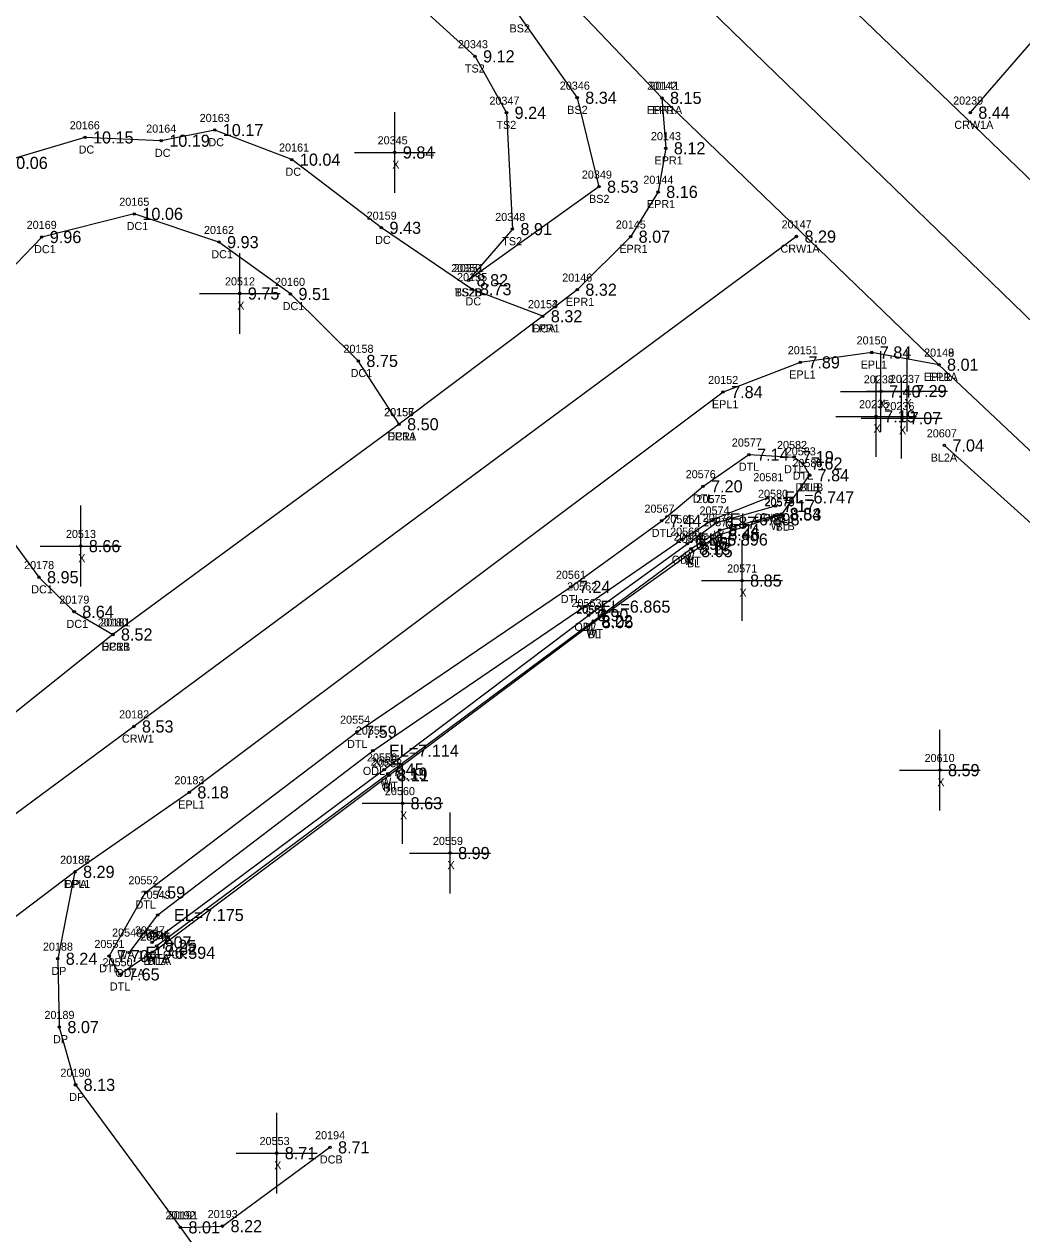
# Model space of a CAD drawing. Extents: x 2608745 to 2610333, y 641917 to 643463.
# Drawn here: x 2608960.7 to 2609084.1, y 642999.4 to 643149.1 of the extents above; entities that cross this region are included whole.
import ezdxf

# ---------------------------------------------------------------- set-up
doc = ezdxf.new("R2010")
doc.units = 0
for name, color, linetype in [('RD_DTM_BkLn1', 7, 'Continuous'), ('RD_DTM_BkLn2', 7, 'Continuous'), ('RD_DTM_BkLn_txCode', 7, 'Continuous'), ('RD_EX_BldgApp', 7, 'Continuous'), ('RD_EX_Conc', 7, 'Continuous'), ('RD_EX_Conc_txCode', 7, 'Continuous'), ('RD_EX_Driveway', 7, 'Continuous'), ('RD_EX_Driveway_txCode', 7, 'Continuous'), ('RD_EX_H2O', 7, 'Continuous'), ('RD_EX_H2O_txCode', 7, 'Continuous'), ('RD_EX_Misc', 7, 'Continuous'), ('RD_EX_Misc_txCode', 7, 'Continuous'), ('RD_EX_Road', 7, 'Continuous'), ('RD_EX_Road_txCode', 7, 'Continuous'), ('RD_EX_TX_Conc_ELEV', 7, 'Continuous'), ('RD_EX_TX_Driveway_ELEV', 7, 'Continuous'), ('RD_EX_TX_H2O_ELEV', 7, 'Continuous'), ('RD_EX_TX_Misc_ELEV', 7, 'Continuous'), ('RD_EX_TX_Road_ELEV', 7, 'Continuous'), ('RD_HC_Survey_ELEV', 7, 'Continuous'), ('RD_HC_Survey_txCode', 7, 'Continuous'), ('RD_SMD_Locator', 7, 'Continuous')]:
    doc.layers.add(name, color=color, linetype=linetype)

msp = doc.modelspace()

# ---------------------------------------------------------------- linework, layer by layer
at = {"layer": 'RD_DTM_BkLn1'}
for points in [[(2608814.73, 643373.65), (2608890.45, 643300.26), (2608962.19, 643231.31), (2609034.91, 643161.19), (2609108.48, 643089.9), (2609179.19, 643022.29), (2609255.71, 642948.78), (2609335.19, 642871.73), (2609410.7, 642798.48), (2609491.67, 642719.95), (2609518.07, 642695.15)], [(2609077.75, 643138.13), (2609090.47, 643152.84), (2609101.55, 643166.78), (2609119.24, 643191.44), (2609138.5, 643219.13), (2609195.83, 643301.54)], [(2609056.24, 643122.81), (2608974.26, 643062.19), (2608891.12, 643000.79)], [(2609074.55, 643096.96), (2609096.36, 643077.36), (2609116.48, 643056.4)], [(2608977.19, 643034.69), (2609005.85, 643056.15), (2609031.16, 643075.1), (2609043.45, 643083.89), (2609046.82, 643085.96), (2609054.43, 643088.41), (2609057.86, 643093.28)]]:
    msp.add_lwpolyline(points, dxfattribs=at)
at = {"layer": 'RD_DTM_BkLn2'}
for points in [[(2608924.3, 643237.42), (2608926.68, 643230.5), (2608943.06, 643211.67), (2609016.47, 643145.1), (2609020.37, 643138.12), (2609021.09, 643123.73), (2609015.67, 643117.4)], [(2608924.3, 643237.42), (2608928.82, 643236.52), (2608949.12, 643217.98), (2609021.97, 643150.06), (2609029.11, 643139.98), (2609031.81, 643128.97), (2609015.67, 643117.4)], [(2608977.07, 643035.04), (2609005.68, 643056.35), (2609031.1, 643075.23), (2609043.19, 643084.18), (2609046.77, 643086.49), (2609054.4, 643088.49)]]:
    msp.add_lwpolyline(points, dxfattribs=at)
at = {"layer": 'RD_EX_BldgApp'}
msp.add_lwpolyline([(2608976.5, 643035.47), (2609005.23, 643056.86), (2609030.55, 643075.96), (2609042.75, 643084.8), (2609046.37, 643087.41), (2609053.65, 643089.48)], dxfattribs=at)
at = {"layer": 'RD_EX_Conc'}
for points in [[(2609024.85, 643112.94), (2609016.08, 643116.29), (2609004.89, 643123.89), (2608993.8, 643132.32), (2608984.26, 643135.98), (2608977.64, 643134.66), (2608968.2, 643135.07), (2608957.58, 643131.92), (2608944.58, 643124.19), (2608938.75, 643122.14), (2608934.12, 643122.55)], [(2609007.07, 643099.58), (2609002.03, 643107.42), (2608993.62, 643115.7), (2608984.79, 643122.12), (2608974.31, 643125.61), (2608962.85, 643122.75), (2608953.28, 643112.83), (2608950.49, 643102.09), (2608953.24, 643093.2), (2608962.51, 643080.66), (2608966.87, 643076.38), (2608971.66, 643073.57)], [(2608980.01, 643000.22), (2608985.22, 643000.37), (2608998.52, 643010.12)]]:
    msp.add_lwpolyline(points, dxfattribs=at)
at = {"layer": 'RD_EX_Driveway'}
msp.add_lwpolyline([(2608966.97, 643044.2), (2608964.83, 643033.45), (2608965.03, 643025), (2608967.04, 643017.85), (2608980.01, 643000.22), (2609002.72, 642968.53)], dxfattribs=at)
at = {"layer": 'RD_EX_H2O'}
for points in [[(2608977.19, 643034.69), (2608972.54, 643031.52), (2608971.2, 643033.78), (2608975.7, 643041.66), (2609001.88, 643061.53), (2609028.33, 643079.46), (2609039.58, 643087.64), (2609044.68, 643091.9), (2609050.37, 643095.82), (2609055.96, 643095.52), (2609057.04, 643094.73), (2609057.86, 643093.28)], [(2608973.68, 643034.19), (2608977.21, 643038.87), (2609003.83, 643059.19), (2609030, 643077.02), (2609042.06, 643085.32), (2609045.99, 643087.82), (2609052.74, 643090.53)]]:
    msp.add_lwpolyline(points, dxfattribs=at)
at = {"layer": 'RD_EX_Misc'}
for p, q in [((2609006.54, 643128.21), (2609006.54, 643138.21)), ((2609001.54, 643133.21), (2609011.54, 643133.21)), ((2608987.36, 643110.76), (2608987.36, 643120.76)), ((2608982.36, 643115.76), (2608992.36, 643115.76)), ((2609066.7, 643098.64), (2609066.7, 643108.64)), ((2609069.93, 643098.69), (2609069.93, 643108.69)), ((2609066.1, 643095.56), (2609066.1, 643105.56)), ((2609069.26, 643095.34), (2609069.26, 643105.34)), ((2609061.7, 643103.64), (2609071.7, 643103.64)), ((2609064.93, 643103.69), (2609074.93, 643103.69)), ((2609061.1, 643100.56), (2609071.1, 643100.56)), ((2609064.26, 643100.34), (2609074.26, 643100.34)), ((2608967.68, 643079.51), (2608967.68, 643089.51)), ((2609049.51, 643075.24), (2609049.51, 643085.24)), ((2608962.68, 643084.51), (2608972.68, 643084.51)), ((2609044.51, 643080.24), (2609054.51, 643080.24)), ((2609074, 643051.79), (2609074, 643061.79)), ((2609007.5, 643047.69), (2609007.5, 643057.69)), ((2609069, 643056.79), (2609079, 643056.79)), ((2609002.5, 643052.69), (2609012.5, 643052.69)), ((2609013.38, 643041.53), (2609013.38, 643051.53)), ((2609008.38, 643046.53), (2609018.38, 643046.53)), ((2608991.93, 643004.4), (2608991.93, 643014.4)), ((2608986.93, 643009.4), (2608996.93, 643009.4))]:
    msp.add_line(p, q, dxfattribs=at)
at = {"layer": 'RD_EX_Road'}
for points in [[(2608806.89, 643364.99), (2608810.18, 643361.1), (2608820.75, 643351.25), (2608881.81, 643292.24), (2608917.83, 643257.49), (2608933.21, 643242.71), (2608954.07, 643222.83), (2609026.06, 643154.19), (2609039.6, 643139.96), (2609073.88, 643106.95), (2609100.48, 643081.89), (2609124.19, 643058.87), (2609171.61, 643013.71), (2609183.19, 643002.28), (2609197.91, 642988.37), (2609247.59, 642940.95), (2609328.02, 642863.6), (2609402.61, 642790.3), (2609474.23, 642720.69), (2609483.84, 642711.58), (2609495.78, 642699.92), (2609509.81, 642686.45)], [(2609058.51, 643155.46), (2609096.06, 643119.37), (2609116.51, 643099.11), (2609162.4, 643055.35), (2609177.21, 643041.34), (2609188.35, 643030.96), (2609199.91, 643019.76), (2609205.8, 643014.04), (2609217.13, 643003.17), (2609235.83, 642983.9), (2609237.03, 642983.51), (2609256.8, 642965.04), (2609258.49, 642962.51), (2609263.65, 642957.66), (2609344.71, 642879.89), (2609418.83, 642806.19), (2609500.61, 642728.46), (2609512.38, 642716.82), (2609526.19, 642703.5)], [(2609039.6, 643139.96), (2609040.08, 643133.73), (2609039.13, 643128.33), (2609035.72, 643122.79), (2609029.12, 643116.23), (2609024.85, 643112.94), (2609007.07, 643099.58), (2608971.66, 643073.57), (2608951.45, 643057.43), (2608918.97, 643034.33), (2608905.4, 643024.24), (2608885.4, 643009.36)], [(2609073.88, 643106.95), (2609065.56, 643108.46), (2609056.72, 643107.24), (2609047.16, 643103.56), (2608981.11, 643054.04), (2608966.97, 643044.2), (2608926.38, 643013.48), (2608922.5, 643010.56), (2608906.31, 642998.78), (2608898.21, 642992.72)]]:
    msp.add_lwpolyline(points, dxfattribs=at)
at = {"layer": 'RD_SMD_Locator'}
for centre in [(2609016.47, 643145.1), (2609029.11, 643139.98), (2609039.6, 643139.96), (2609039.6, 643139.96), (2609020.37, 643138.12), (2609077.75, 643138.13), (2608984.26, 643135.98), (2608968.2, 643135.07), (2608977.64, 643134.66), (2609006.54, 643133.21), (2609040.08, 643133.73), (2608993.8, 643132.32), (2609031.81, 643128.97), (2609039.13, 643128.33), (2608974.31, 643125.61), (2608962.85, 643122.75), (2609004.89, 643123.89), (2609021.09, 643123.73), (2609035.72, 643122.79), (2609056.24, 643122.81), (2608984.79, 643122.12), (2609015.67, 643117.4), (2609015.67, 643117.4), (2608987.36, 643115.76), (2608993.62, 643115.7), (2609016.08, 643116.29), (2609029.12, 643116.23), (2609024.85, 643112.94), (2609024.85, 643112.94), (2609065.56, 643108.46), (2609002.03, 643107.42), (2609056.72, 643107.24), (2609073.88, 643106.95), (2609073.88, 643106.95), (2609047.16, 643103.56), (2609066.7, 643103.64), (2609069.93, 643103.69), (2609066.1, 643100.56), (2609069.26, 643100.34), (2609007.07, 643099.58), (2609007.07, 643099.58), (2609050.37, 643095.82), (2609055.96, 643095.52), (2609074.55, 643096.96), (2609057.04, 643094.73), (2609057.86, 643093.28), (2609057.86, 643093.28), (2609044.68, 643091.9), (2609052.74, 643090.53), (2609053.65, 643089.48), (2609054.4, 643088.49), (2609054.43, 643088.41), (2609039.58, 643087.64), (2609045.99, 643087.82), (2609046.37, 643087.41), (2609046.77, 643086.49), (2609042.06, 643085.32), (2609046.82, 643085.96), (2608967.68, 643084.51), (2609042.75, 643084.8), (2609043.19, 643084.18), (2609043.45, 643083.89), (2608962.51, 643080.66), (2609028.33, 643079.46), (2609049.51, 643080.24), (2608966.87, 643076.38), (2609030, 643077.02), (2609030.55, 643075.96), (2609031.1, 643075.23), (2609031.16, 643075.1), (2608971.66, 643073.57), (2608971.66, 643073.57), (2608974.26, 643062.19), (2609001.88, 643061.53), (2609003.83, 643059.19), (2609005.23, 643056.86), (2609074, 643056.79), (2609005.68, 643056.35), (2609005.85, 643056.15), (2608981.11, 643054.04), (2609007.5, 643052.69), (2609013.38, 643046.53), (2608966.97, 643044.2), (2608966.97, 643044.2), (2608975.7, 643041.66), (2608977.21, 643038.87), (2608973.68, 643034.19), (2608976.5, 643035.47), (2608977.07, 643035.04), (2608977.19, 643034.69), (2608977.19, 643034.69), (2608964.83, 643033.45), (2608971.2, 643033.78), (2608972.54, 643031.52), (2608965.03, 643025), (2608967.04, 643017.85), (2608991.93, 643009.4), (2608998.52, 643010.12), (2608980.01, 643000.22), (2608980.01, 643000.22), (2608985.22, 643000.37)]:
    msp.add_circle(centre, 0.15, dxfattribs=at)

# ---------------------------------------------------------------- texts
at = {"layer": 'RD_DTM_BkLn_txCode'}
for s, p in [('BS2', (2609020.74, 643148.06)), ('20343', (2609014.35, 643146.1)), ('TS2', (2609015.22, 643143.1)), ('20346', (2609026.96, 643140.98)), ('20347', (2609018.25, 643139.12)), ('BS2', (2609027.88, 643137.98)), ('TS2', (2609019.12, 643136.12)), ('20349', (2609029.69, 643129.97)), ('BS2', (2609030.58, 643126.97)), ('20348', (2609018.97, 643124.73)), ('TS2', (2609019.84, 643121.73)), ('20350', (2609013.52, 643118.4)), ('20351', (2609013.84, 643118.4)), ('TS2B', (2609013.96, 643115.4)), ('BS2B', (2609013.97, 643115.4)), ('20607', (2609072.37, 643097.96)), ('BL2A', (2609072.86, 643094.96)), ('20585', (2609055.74, 643094.28)), ('BLB', (2609056.63, 643091.28)), ('20579', (2609052.31, 643089.41)), ('20573', (2609044.7, 643086.96)), ('BL', (2609053.67, 643086.41)), ('20570', (2609041.3, 643084.89)), ('BL', (2609046.06, 643083.96)), ('BL', (2609042.7, 643081.89)), ('20565', (2609029.02, 643076.1)), ('BL', (2609030.41, 643073.1)), ('20558', (2609003.73, 643057.15)), ('BL', (2609005.09, 643054.15)), ('20545', (2608975.07, 643035.69)), ('BLA', (2608975.94, 643032.69))]:
    msp.add_text(s, height=1, dxfattribs=at).set_placement(p)
at = {"layer": 'RD_EX_Conc_txCode'}
for s, p in [('20163', (2608982.4, 643136.98)), ('20166', (2608966.32, 643136.07)), ('20164', (2608975.78, 643135.66)), ('DC', (2608983.48, 643133.98)), ('DC', (2608967.42, 643133.07)), ('DC', (2608976.86, 643132.66)), ('20161', (2608992.22, 643133.32)), ('DC', (2608993.02, 643130.32)), ('20165', (2608972.45, 643126.61)), ('20159', (2609003.06, 643124.89)), ('20169', (2608960.99, 643123.75)), ('DC1', (2608973.36, 643123.61)), ('20162', (2608982.93, 643123.12)), ('DC', (2609004.11, 643121.89)), ('DC1', (2608961.91, 643120.75)), ('DC1', (2608983.84, 643120.12)), ('20155', (2609014.25, 643117.29)), ('20160', (2608991.72, 643116.7)), ('DC', (2609015.3, 643114.29)), ('DC1', (2608992.67, 643113.7)), ('20154', (2609023.02, 643113.94)), ('DCA', (2609023.58, 643110.94)), ('20158', (2609000.19, 643108.42)), ('DC1', (2609001.08, 643105.42)), ('20157', (2609005.23, 643100.58)), ('DC1A', (2609005.63, 643097.58)), ('20178', (2608960.67, 643081.66)), ('DC1', (2608961.56, 643078.66)), ('20179', (2608965.03, 643077.38)), ('DC1', (2608965.92, 643074.38)), ('20180', (2608969.79, 643074.57)), ('DC1B', (2608970.24, 643071.57)), ('20194', (2608996.68, 643011.12)), ('DCB', (2608997.27, 643008.12)), ('20192', (2608978.17, 643001.22)), ('20193', (2608983.39, 643001.37))]:
    msp.add_text(s, height=1, dxfattribs=at).set_placement(p)
at = {"layer": 'RD_EX_Driveway_txCode'}
for s, p in [('20187', (2608965.14, 643045.2)), ('DPA', (2608965.71, 643042.2)), ('20188', (2608963, 643034.45)), ('DP', (2608964.05, 643031.45)), ('20189', (2608963.19, 643026)), ('DP', (2608964.25, 643023)), ('20190', (2608965.17, 643018.85)), ('DP', (2608966.26, 643015.85)), ('20191', (2608978.46, 643001.22))]:
    msp.add_text(s, height=1, dxfattribs=at).set_placement(p)
at = {"layer": 'RD_EX_H2O_txCode'}
for s, p in [('20577', (2609048.25, 643096.82)), ('20582', (2609053.84, 643096.52)), ('20583', (2609054.92, 643095.73)), ('DTL', (2609049.12, 643093.82)), ('DTL', (2609054.72, 643093.52)), ('20584', (2609055.74, 643094.28)), ('20576', (2609042.54, 643092.9)), ('20581', (2609050.91, 643092.53)), ('DTL', (2609055.8, 643092.73)), ('DTLB', (2609056.14, 643091.28)), ('20567', (2609037.44, 643088.64)), ('DTL', (2609043.43, 643089.9)), ('20575', (2609043.87, 643089.82)), ('20566', (2609039.9, 643087.32)), ('ODLB', (2609051.03, 643087.53)), ('DTL', (2609038.34, 643085.64)), ('ODL', (2609044.74, 643084.82)), ('ODL', (2609040.82, 643082.32)), ('20561', (2609026.48, 643080.46)), ('20562', (2609027.86, 643079.02)), ('DTL', (2609027.09, 643077.46)), ('ODL', (2609028.76, 643074.02)), ('20554', (2608999.77, 643062.53)), ('20555', (2609001.72, 643061.19)), ('DTL', (2609000.64, 643059.53)), ('ODL', (2609002.59, 643056.19)), ('20552', (2608973.58, 643042.66)), ('20549', (2608975.09, 643040.87)), ('DTL', (2608974.46, 643039.66)), ('20551', (2608969.37, 643034.78)), ('20548', (2608971.56, 643036.19)), ('20546', (2608975.04, 643035.69)), ('ODL', (2608975.97, 643035.87)), ('DTL', (2608969.96, 643031.78)), ('20550', (2608970.38, 643032.52)), ('DTLA', (2608975.45, 643032.69)), ('ODLA', (2608971.95, 643031.19)), ('DTL', (2608971.29, 643029.52))]:
    msp.add_text(s, height=1, dxfattribs=at).set_placement(p)
at = {"layer": 'RD_EX_Misc_txCode'}
for s, p in [('20345', (2609004.42, 643134.21)), ('X', (2609006.23, 643131.21)), ('20512', (2608985.53, 643116.76)), ('X', (2608987.05, 643113.76)), ('20238', (2609064.58, 643104.64)), ('20237', (2609067.81, 643104.69)), ('20235', (2609063.99, 643101.56)), ('X', (2609066.38, 643101.64)), ('20236', (2609067.12, 643101.34)), ('X', (2609069.61, 643101.69)), ('X', (2609065.79, 643098.56)), ('X', (2609068.94, 643098.34)), ('20580', (2609051.49, 643090.48)), ('20578', (2609052.28, 643089.49)), ('20574', (2609044.25, 643088.41)), ('20572', (2609044.65, 643087.49)), ('WB', (2609052.8, 643087.48)), ('20568', (2609040.61, 643085.8)), ('WTB', (2609053.07, 643086.49)), ('20513', (2608965.85, 643085.51)), ('20569', (2609041.05, 643085.18)), ('WT', (2609045.91, 643084.49)), ('W', (2609046, 643085.41)), ('W', (2609042.38, 643082.8)), ('X', (2608967.37, 643082.51)), ('WT', (2609042.33, 643082.18)), ('20571', (2609047.67, 643081.24)), ('X', (2609049.19, 643078.24)), ('20563', (2609028.4, 643076.96)), ('20564', (2609028.96, 643076.23)), ('W', (2609030.17, 643073.96)), ('WT', (2609030.24, 643073.23)), ('20556', (2609003.09, 643057.86)), ('20557', (2609003.56, 643057.35)), ('20610', (2609072.1, 643057.79)), ('WT', (2609004.82, 643054.35)), ('W', (2609004.86, 643054.86)), ('X', (2609073.68, 643054.79)), ('20560', (2609005.32, 643053.69)), ('X', (2609007.19, 643050.69)), ('20559', (2609011.26, 643047.53)), ('X', (2609013.06, 643044.53)), ('20547', (2608974.38, 643036.47)), ('20544', (2608974.95, 643036.04)), ('WA 14BLOCK', (2608972.21, 643033.47)), ('WTA', (2608975.72, 643033.04)), ('20553', (2608989.81, 643010.4)), ('X', (2608991.62, 643007.4))]:
    msp.add_text(s, height=1, dxfattribs=at).set_placement(p)
at = {"layer": 'RD_EX_Road_txCode'}
for s, p in [('20142', (2609037.77, 643140.96)), ('20141', (2609038.05, 643140.96)), ('EPR1A', (2609037.72, 643137.96)), ('EPR', (2609038.37, 643137.96)), ('20143', (2609038.24, 643134.73)), ('EPR1', (2609038.68, 643131.73)), ('20144', (2609037.3, 643129.33)), ('EPR1', (2609037.74, 643126.33)), ('20145', (2609033.89, 643123.79)), ('EPR1', (2609034.33, 643120.79)), ('20146', (2609027.26, 643117.23)), ('EPR1', (2609027.72, 643114.23)), ('20153', (2609023.02, 643113.94)), ('EPR1', (2609023.46, 643110.94)), ('20151', (2609055.17, 643108.24)), ('20150', (2609063.69, 643109.46)), ('20148', (2609072.04, 643107.95)), ('20149', (2609072.04, 643107.95)), ('EPL1', (2609055.35, 643105.24)), ('EPL1', (2609064.19, 643106.46)), ('20152', (2609045.32, 643104.56)), ('EPL1A', (2609072.02, 643104.95)), ('EPR', (2609072.65, 643104.95)), ('EPL1', (2609045.79, 643101.56)), ('20156', (2609005.21, 643100.58)), ('EPR1', (2609005.67, 643097.58)), ('20181', (2608970.11, 643074.57)), ('EPR1', (2608970.27, 643071.57)), ('20183', (2608979.27, 643055.04)), ('EPL1', (2608979.74, 643052.04)), ('20186', (2608965.12, 643045.2)), ('EPL1', (2608965.6, 643042.2))]:
    msp.add_text(s, height=1, dxfattribs=at).set_placement(p)
at = {"layer": 'RD_EX_TX_Conc_ELEV'}
for s, p in [('10.17', (2608985.26, 643135.23)), ('10.15', (2608969.2, 643134.32)), ('10.19', (2608978.64, 643133.91)), ('10.04', (2608994.8, 643131.57)), ('10.06', (2608958.58, 643131.17)), ('10.06', (2608975.31, 643124.86)), ('9.43', (2609005.89, 643123.14)), ('9.96', (2608963.85, 643122)), ('9.93', (2608985.79, 643121.37)), ('8.73', (2609017.08, 643115.54)), ('9.51', (2608994.62, 643114.95)), ('8.32', (2609025.85, 643112.19)), ('8.75', (2609003.03, 643106.67)), ('8.50', (2609008.07, 643098.83)), ('8.95', (2608963.51, 643079.91)), ('8.64', (2608967.87, 643075.63)), ('8.52', (2608972.66, 643072.82)), ('8.71', (2608999.52, 643009.37)), ('8.01', (2608981.01, 642999.47)), ('8.22', (2608986.22, 642999.62))]:
    msp.add_text(s, height=1.5, dxfattribs=at).set_placement(p)
at = {"layer": 'RD_EX_TX_Driveway_ELEV'}
for s, p in [('8.29', (2608967.97, 643043.45)), ('8.24', (2608965.83, 643032.7)), ('8.07', (2608966.03, 643024.25)), ('8.13', (2608968.04, 643017.1)), ('8.01', (2608981.01, 642999.47))]:
    msp.add_text(s, height=1.5, dxfattribs=at).set_placement(p)
at = {"layer": 'RD_EX_TX_H2O_ELEV'}
for s, p in [('7.14', (2609051.37, 643095.07)), ('7.19', (2609056.96, 643094.77)), ('7.62', (2609058.04, 643093.98)), ('7.20', (2609045.68, 643091.15)), ('7.84', (2609058.86, 643092.53)), ('EL=6.747', (2609054.74, 643089.78)), ('7.44', (2609040.58, 643086.89)), ('EL=6.898', (2609047.99, 643087.07)), ('EL=6.896', (2609044.06, 643084.57)), ('7.24', (2609029.33, 643078.71)), ('EL=6.865', (2609032, 643076.27)), ('7.59', (2609002.88, 643060.78)), ('EL=7.114', (2609005.83, 643058.44)), ('7.59', (2608976.7, 643040.91)), ('EL=7.175', (2608979.21, 643038.12)), ('7.70', (2608972.2, 643033.03)), ('EL=6.594', (2608975.68, 643033.44)), ('7.82', (2608978.19, 643033.94)), ('7.65', (2608973.54, 643030.77))]:
    msp.add_text(s, height=1.5, dxfattribs=at).set_placement(p)
at = {"layer": 'RD_EX_TX_Misc_ELEV'}
for s, p in [('9.12', (2609017.47, 643144.35)), ('8.34', (2609030.11, 643139.23)), ('9.24', (2609021.37, 643137.37)), ('9.84', (2609007.54, 643132.46)), ('8.53', (2609032.81, 643128.22)), ('8.91', (2609022.09, 643122.98)), ('8.82', (2609016.67, 643116.65)), ('8.82', (2609016.67, 643116.65)), ('9.75', (2608988.36, 643115.01)), ('7.40', (2609067.7, 643102.89)), ('7.29', (2609070.93, 643102.94)), ('7.19', (2609067.1, 643099.81)), ('7.07', (2609070.26, 643099.59)), ('7.04', (2609075.55, 643096.21)), ('7.84', (2609058.86, 643092.53)), ('7.17', (2609054.65, 643088.73)), ('6.87', (2609047.37, 643086.66)), ('8.84', (2609055.4, 643087.74)), ('8.53', (2609055.43, 643087.66)), ('8.24', (2609047.77, 643085.74)), ('8.46', (2609047.82, 643085.21)), ('8.66', (2608968.68, 643083.76)), ('6.96', (2609043.75, 643084.05)), ('8.13', (2609044.19, 643083.43)), ('8.05', (2609044.45, 643083.14)), ('8.85', (2609050.51, 643079.49)), ('6.90', (2609031.55, 643075.21)), ('8.22', (2609032.1, 643074.48)), ('8.06', (2609032.16, 643074.35)), ('7.45', (2609006.23, 643056.11)), ('8.19', (2609006.68, 643055.6)), ('8.11', (2609006.85, 643055.4)), ('8.59', (2609075, 643056.04)), ('8.63', (2609008.5, 643051.94)), ('8.99', (2609014.38, 643045.78)), ('7.07', (2608977.5, 643034.72)), ('8.25', (2608978.07, 643034.29)), ('7.82', (2608978.19, 643033.94)), ('8.71', (2608992.93, 643008.65))]:
    msp.add_text(s, height=1.5, dxfattribs=at).set_placement(p)
at = {"layer": 'RD_EX_TX_Road_ELEV'}
for s, p in [('8.15', (2609040.6, 643139.21)), ('8.15', (2609040.6, 643139.21)), ('8.12', (2609041.08, 643132.98)), ('8.16', (2609040.13, 643127.58)), ('8.07', (2609036.72, 643122.04)), ('8.32', (2609030.12, 643115.48)), ('8.32', (2609025.85, 643112.19)), ('7.84', (2609066.56, 643107.71)), ('7.89', (2609057.72, 643106.49)), ('8.01', (2609074.88, 643106.2)), ('8.01', (2609074.88, 643106.2)), ('7.84', (2609048.16, 643102.81)), ('8.50', (2609008.07, 643098.83)), ('8.52', (2608972.66, 643072.82)), ('8.18', (2608982.11, 643053.29)), ('8.29', (2608967.97, 643043.45))]:
    msp.add_text(s, height=1.5, dxfattribs=at).set_placement(p)
at = {"layer": 'RD_HC_Survey_ELEV'}
for s, p in [('8.44', (2609078.75, 643137.38)), ('8.29', (2609057.24, 643122.06)), ('8.53', (2608975.26, 643061.44))]:
    msp.add_text(s, height=1.5, dxfattribs=at).set_placement(p)
at = {"layer": 'RD_HC_Survey_txCode'}
for s, p in [('20239', (2609075.63, 643139.13)), ('CRW1A', (2609075.78, 643136.13)), ('20147', (2609054.41, 643123.81)), ('CRW1A', (2609054.27, 643120.81)), ('20182', (2608972.43, 643063.19)), ('CRW1', (2608972.78, 643060.19))]:
    msp.add_text(s, height=1, dxfattribs=at).set_placement(p)

doc.saveas('drawing.dxf')
